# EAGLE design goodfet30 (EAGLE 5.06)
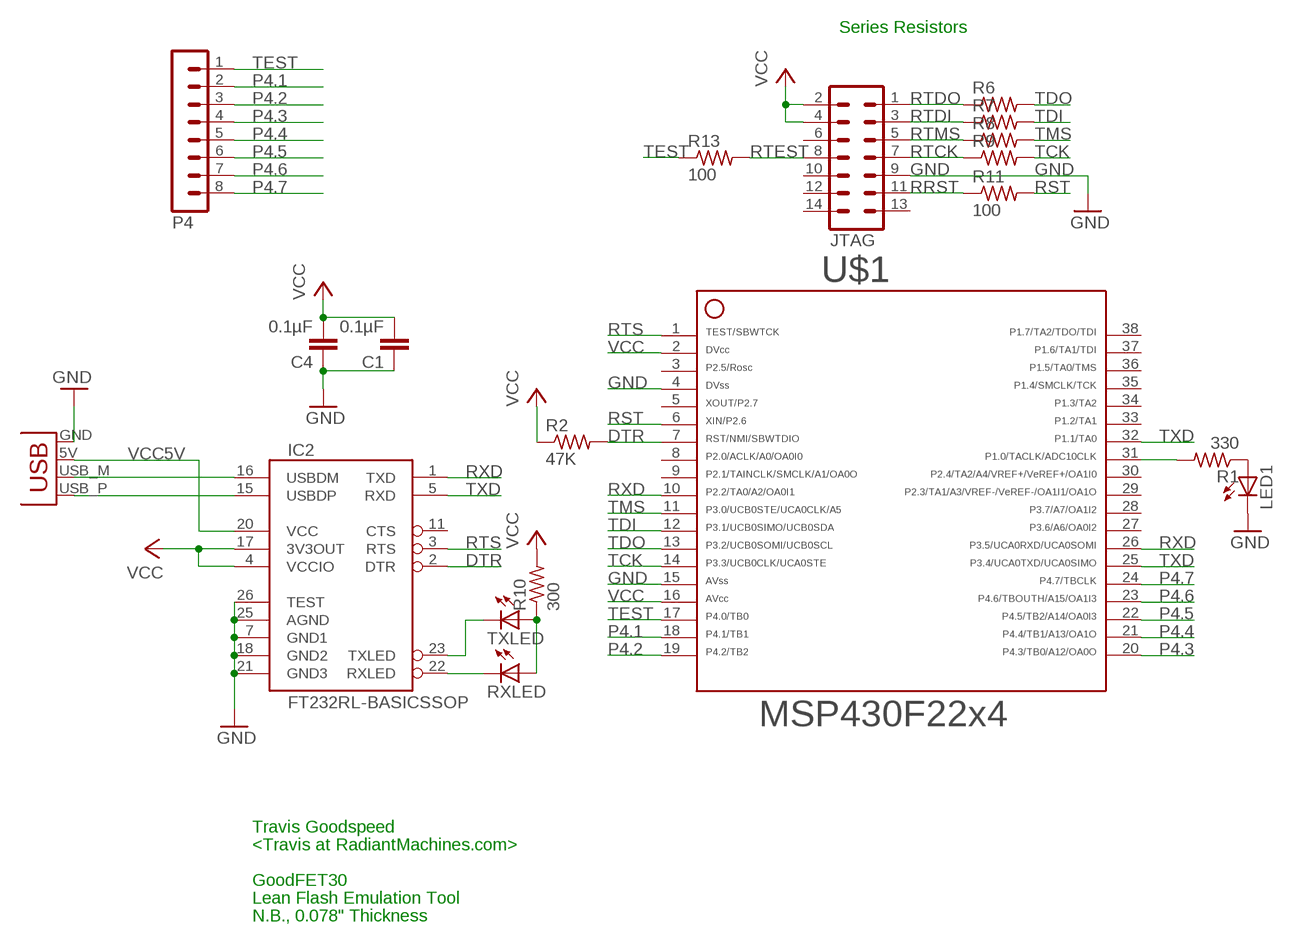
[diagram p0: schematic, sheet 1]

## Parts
C1  0.1µF  C-EUC0603  [C0603]
C4  0.1µF  C-EUC0603  [C0603]
IC2  FT232RL-BASICSSOP  [SSOP28DB]
JTAG  MA07-2  [MA07-2]
LED1  LEDCHIP-LED0603  [CHIP-LED0603]
P4  MA08-1  [MA08-1]
R1  330  R-US_R0603  [R0603]
R2  47K  R-US_R0603  [R0603]
R6  100  R-US_R0603  [R0603]
R7  100  R-US_R0603  [R0603]
R8  100  R-US_R0603  [R0603]
R9  100  R-US_R0603  [R0603]
R10  300  R-US_R0603  [R0603]
R11  100  R-US_R0603  [R0603]
R13  100  R-US_R0603  [R0603]
RXLED  LEDCHIP-LED0603  [CHIP-LED0603]
TXLED  LEDCHIP-LED0603  [CHIP-LED0603]
U$1  F22X4---DA38  [DA38]
X1  USBPCB  [USB-A-PCB]

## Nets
DTR: IC2.2(DTR) R2.2 U$1.7
GND: C1.1 C4.1 IC2.7(GND1) IC2.18(GND2) IC2.21(GND3) IC2.25(AGND) IC2.26(TEST) JTAG.9 LED1.C U$1.4 U$1.15 X1.GND
N$3: IC2.15(USBDP) X1.USB_P(D+)
N$4: IC2.16(USBDM) X1.USB_M(D-)
N$6: IC2.22(RXLED) RXLED.C
N$7: IC2.23(TXLED) TXLED.C
N$8: R10.1 RXLED.A TXLED.A
N$9: R1.2 U$1.31
N$10: LED1.A R1.1
P4.1: P4.2 U$1.18
P4.2: P4.3 U$1.19
P4.3: P4.4 U$1.20
P4.4: P4.5 U$1.21
P4.5: P4.6 U$1.22
P4.6: P4.7 U$1.23
P4.7: P4.8 U$1.24
RRST: JTAG.11 R11.1
RST: R11.2 U$1.6
RTCK: JTAG.7 R9.1
RTDI: JTAG.3 R7.1
RTDO: JTAG.1 R6.1
RTEST: JTAG.8 R13.2
RTMS: JTAG.5 R8.1
RTS: IC2.3(RTS) U$1.1
RXD: IC2.1(TXD) U$1.10 U$1.26
TCK: R9.2 U$1.14
TDI: R7.2 U$1.12
TDO: R6.2 U$1.13
TEST: P4.1 R13.1 U$1.17
TMS: R8.2 U$1.11
TXD: IC2.5(RXD) U$1.25 U$1.32
VCC: C1.2 C4.2 IC2.4(VCCIO) IC2.17(3V3OUT) JTAG.2 JTAG.4 R2.1 R10.2 U$1.2 U$1.16
VCC5V: IC2.20(VCC) X1.5V(VBUS)
Unconnected: IC2.11(CTS) JTAG.6 JTAG.10 JTAG.12 JTAG.13 JTAG.14 U$1.3 U$1.5 U$1.8 U$1.9 U$1.27 U$1.28 U$1.29 U$1.30 U$1.33 U$1.34 U$1.35 U$1.36 U$1.37 U$1.38

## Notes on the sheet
- Series Resistors
- Travis Goodspeed
- <Travis at RadiantMachines.com>
- GoodFET30
- Lean Flash Emulation Tool
- N.B., 0.078" Thickness

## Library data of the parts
C1 C4 = rcl:C-EU: CAPACITOR, European symbol
IC2 = SparkFun:FT232RL-BASIC: USB UART This is the simplified version of the FT232RL unit. Only what you need, nothing you don't. Spark Fun Electronics SKU : COM-00650
JTAG = con-lstb:MA07-2: PIN HEADER
LED1 RXLED TXLED = led:LED: LED
P4 = con-lstb:MA08-1: PIN HEADER
R1 R2 R10 = rcl:R-US_: RESISTOR, American symbol
R6-R9 R11 R13 = resistor:R-US_: RESISTOR, American symbol
U$1 = TI_MSP430_v13:F22X4---DA38: ***MSP430F22x4***DA38
X1 = SparkFun:USB: USB Connectors USB-B-PTH is fully proven SKU : PRT-00139 USB-miniB is fully proven SKU : PRT-00587 USB-A-PCB is untested. USB-A-H is throughly reviewed, but untested. Spark Fun Electronics SKU : PRT-00437 USB-B-SMT is throughly reviewed, but untested. Needs silkscreen touching up. USB-A-S has not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

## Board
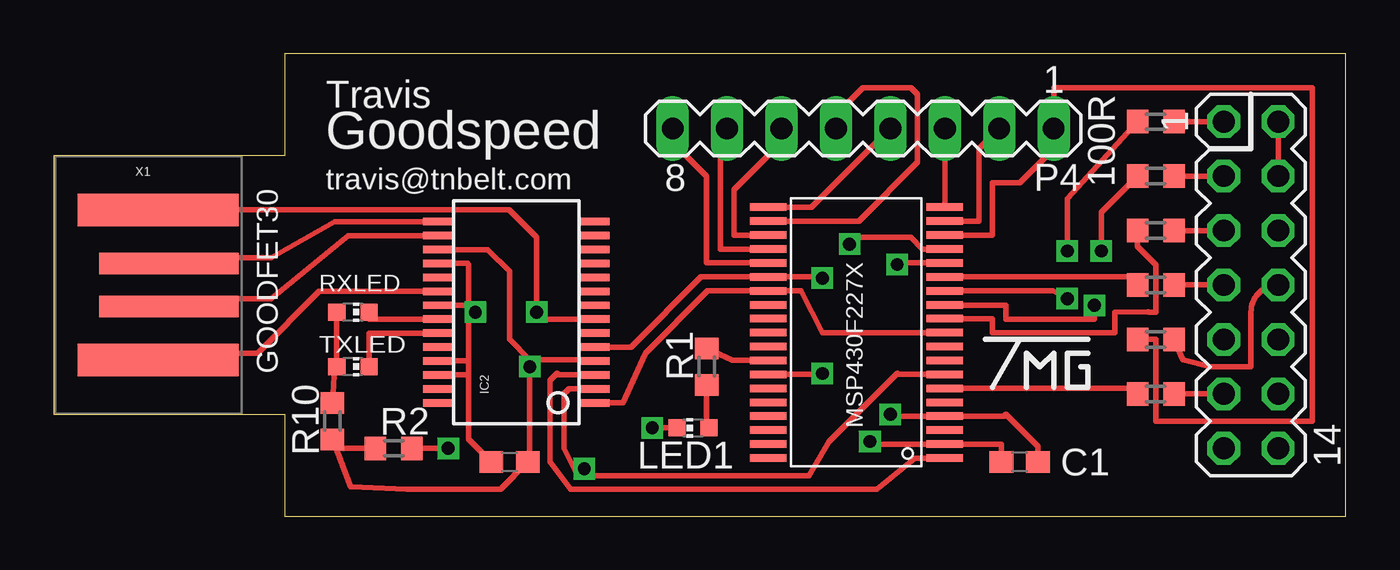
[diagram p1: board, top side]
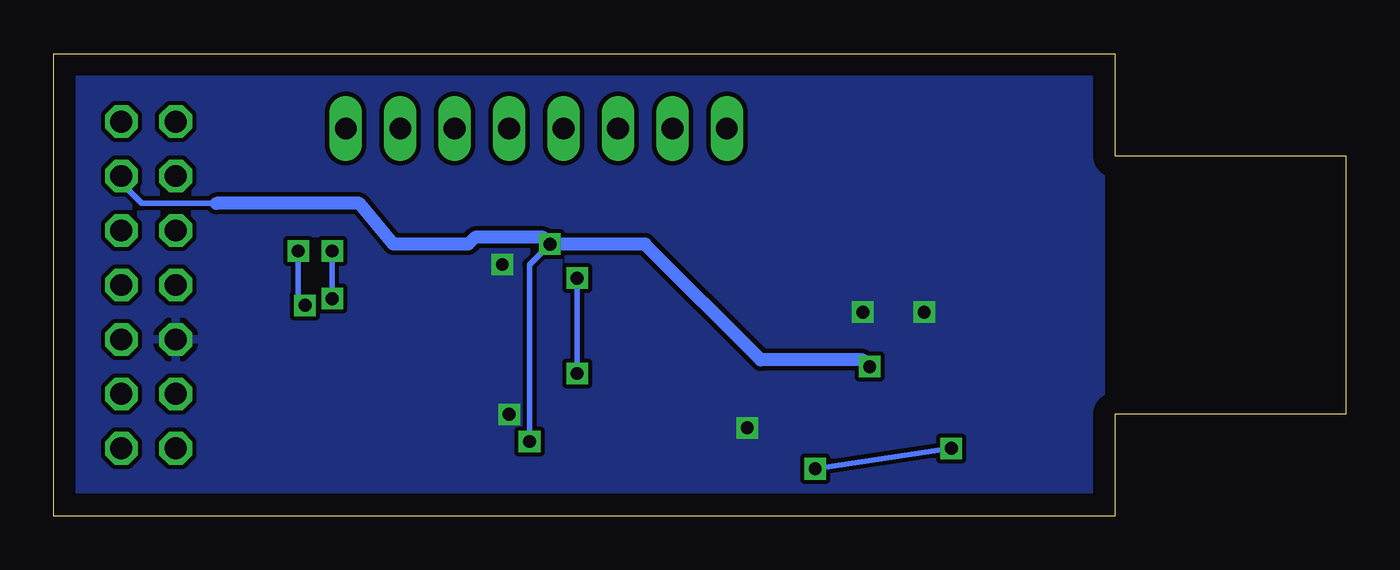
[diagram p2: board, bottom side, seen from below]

Size 60.31 x 21.59 mm. Coordinates in mm from the lower left corner, seen from the top.
Outline: 10.79,0 60.31,0 60.31,21.59 10.79,21.59 10.79,16.83 0,16.83 0,4.76 10.79,4.76 10.79,0
Copper layers (1*16): Top 0.035mm / dielectric 1.5mm / Bottom 0.035mm
Design rules "default *": minimum track width 10mil, minimum drill 10mil, track to track 8mil, track to pad 8mil, pad to pad 8mil, via to via 8mil, smd to smd 8mil, copper to edge 40mil, drill to drill 10mil, minimum pad ring 10mil, minimum via ring 8mil, stop-mask expansion 4mil, vias tented up to drill 0mil, thermal gap 10mil

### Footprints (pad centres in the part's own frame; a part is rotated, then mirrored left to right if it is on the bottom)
C0603 = smd 1.1 x 1: 1 -0.85,0; 2 0.85,0
SSOP28DB = smd 0.348 x 1.397: 1 -4.225,-3.656; 2 -3.575,-3.656; 3 -2.925,-3.656; 4 -2.275,-3.656; 5 -1.625,-3.656; 6 -0.975,-3.656; 7 -0.325,-3.656; 8 0.325,-3.656; 9 0.975,-3.656; 10 1.625,-3.656; 11 2.275,-3.656; 12 2.925,-3.656; 13 3.575,-3.656; 14 4.225,-3.656; 15 4.225,3.656; 16 3.575,3.656; 17 2.925,3.656; 18 2.275,3.656; 19 1.625,3.656; 20 0.975,3.656; 21 0.325,3.656; 22 -0.325,3.656; 23 -0.975,3.656; 24 -1.625,3.656; 25 -2.275,3.656; 26 -2.925,3.656; 27 -3.575,3.656; 28 -4.225,3.656
MA07-2 = drill 1.016 octagon: 1 -7.62,-1.27; 2 -7.62,1.27; 3 -5.08,-1.27; 4 -5.08,1.27; 5 -2.54,-1.27; 6 -2.54,1.27; 7 0,-1.27; 8 0,1.27; 9 2.54,-1.27; 10 2.54,1.27; 11 5.08,-1.27; 12 5.08,1.27; 13 7.62,-1.27; 14 7.62,1.27
CHIP-LED0603 = smd 0.8 x 0.8: A 0,-0.75; C 0,0.75
MA08-1 = drill 1.016 long: 1 -8.89,0; 2 -6.35,0; 3 -3.81,0; 4 -1.27,0; 5 1.27,0; 6 3.81,0; 7 6.35,0; 8 8.89,0
R0603 = smd 1 x 1.1: 1 -0.85,0; 2 0.85,0
DA38 = smd 0.35 x 1.705: 1 -5.85,-4.12; 2 -5.2,-4.12; 3 -4.55,-4.12; 4 -3.9,-4.12; 5 -3.25,-4.12; 6 -2.6,-4.12; 7 -1.95,-4.12; 8 -1.3,-4.12; 9 -0.65,-4.12; 10 0,-4.12; 11 0.65,-4.12; 12 1.3,-4.12; 13 1.95,-4.12; 14 2.6,-4.12; 15 3.25,-4.12; 16 3.9,-4.12; 17 4.55,-4.12; 18 5.2,-4.12; 19 5.85,-4.12; 20 5.85,4.12; 21 5.2,4.12; 22 4.55,4.12; 23 3.9,4.12; 24 3.25,4.12; 25 2.6,4.12; 26 1.95,4.12; 27 1.3,4.12; 28 0.65,4.12; 29 0,4.12; 30 -0.65,4.12; 31 -1.3,4.12; 32 -1.95,4.12; 33 -2.6,4.12; 34 -3.25,4.12; 35 -3.9,4.12; 36 -4.55,4.12; 37 -5.2,4.12; 38 -5.85,4.12
USB-A-PCB = smd 7.5 x 1.5: 5V -0.2,-3.5; GND -0.2,3.5 | smd 6.5 x 1: USB_M 0.3,-1; USB_P 0.3,1

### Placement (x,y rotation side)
C1  45.09,2.54 180 top
C4  21.27,2.54 0 top
IC2  21.59,9.53 90 top
JTAG  55.88,10.79 270 top
LED1  29.85,4.13 90 top
P4  37.78,18.1 180 top
R1  30.48,6.99 90 top
R2  15.88,3.18 0 top
R6  51.44,18.42 180 top
R7  51.44,15.88 180 top
R8  51.44,13.33 180 top
R9  51.44,10.79 180 top
R10  13.02,4.45 270 top
R11  51.44,5.71 180 top
R13  51.44,8.25 0 top
RXLED  13.97,9.53 270 top
TXLED  13.97,6.99 270 top
U$1  37.47,8.57 90 top
X1  5.08,10.79 0 top

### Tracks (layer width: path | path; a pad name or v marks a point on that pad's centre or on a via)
DTR  (via drill 0.6)
  Top 0.254: IC2.2 24.05,5.95 23.81,5.71 23.81,3.18 24.45,1.91 24.76,1.91 | 24.76,1.91 35.24,1.91 36.2,3.49 39.37,6.67 39.41,6.62 U$1.7 | R2.2 v18.41,3.18 | v24.76,2.22 24.76,1.91
  Bottom 0.254: v18.41,3.18 v24.76,2.22
GND  (via drill 0.6)
  Top 0.254: U$1.15 39.45,11.82 v39.37,11.75 | v39.05,4.76 39.05,4.67 U$1.4 44.36,4.67 44.45,4.76 45.94,3.28 C1.1 | IC2.7 22.54,9.2 v22.54,9.53 22.54,13.02 21.27,14.29 X1.GND | IC2.18 19.31,11.8 19.37,11.75 19.37,9.84 | 19.37,6.67 19.37,3.6 C4.1 | 19.37,6.67 19.37,7.3 | 19.37,7.3 19.37,9.84 | IC2.26 19.3,6.6 19.37,6.67 | IC2.25 19.31,7.25 19.37,7.3 | 19.36,9.85 IC2.21 | 19.37,9.84 19.36,9.85 | 19.36,9.85 19.36,9.53 v19.68,9.53 | LED1.C v27.94,4.13
  Bottom 0.254: v39.37,11.75 39.05,11.75 | v39.05,4.76 38.73,4.76 | v22.54,9.53 22.22,9.53 | v19.68,9.53 20,9.53
  pour Bottom: 11.75,20.96 59.37,20.96 59.69,1.27 11.43,1.27 11.43,20.64
N$3
  Top 0.254: IC2.15 13.11,13.75 10.16,12.07 5.65,12.07 X1.USB_P
N$4
  Top 0.254: IC2.16 13.73,13.1 10.16,10.16 5.75,10.16 X1.USB_M
N$6
  Top 0.254: IC2.22 14.72,9.2 RXLED.C
N$7
  Top 0.254: IC2.23 14.72,8.55 TXLED.C
N$8
  Top 0.254: RXLED.A TXLED.A 13.12,6.99 R10.1
N$9
  Top 0.254: U$1.31 31.68,7.27 R1.2
N$10
  Top 0.254: R1.1 30.48,4.33 LED1.A
P4.1
  Top 0.254: U$1.18 43.18,13.77 43.18,17.14 P4.2
P4.2
  Top 0.254: U$1.19 41.59,14.43 P4.3
P4.3
  Top 0.254: U$1.20 35.38,14.42 P4.4
P4.4
  Top 0.254: U$1.21 37.59,13.77 40.32,16.51 40.32,19.68 40.01,20 37.78,20 36.51,18.73 P4.5
P4.5
  Top 0.254: U$1.22 31.75,13.12 31.75,15.24 33.97,17.46 P4.6
P4.6
  Top 0.254: U$1.23 31.11,12.47 31.11,16.83 P4.7
P4.7
  Top 0.254: U$1.24 30.48,11.82 30.48,15.88 28.89,17.46 P4.8
RRST
  Top 0.254: R11.1 JTAG.11
RST
  Top 0.254: U$1.6 50.33,5.97 R11.2
RTCK
  Top 0.254: R9.1 JTAG.7
RTDI
  Top 0.254: R7.1 JTAG.3
RTDO
  Top 0.254: R6.1 JTAG.1
RTEST
  Top 0.254: R13.2 52.71,7.3 53.98,6.99 55.88,6.99 55.88,9.53 arc-90 JTAG.8
RTMS
  Top 0.254: R8.1 JTAG.5
RTS
  Top 0.254: U$1.1 40.19,2.72 38.42,1.27 24.13,1.27 23.18,2.54 23.18,6.35 23.49,6.67 23.56,6.6 IC2.3
RXD
  Top 0.254: IC2.1 26.57,5.3 27.62,7.62 30.53,10.52 U$1.26 34.88,10.52 35.88,8.57 U$1.10
TCK
  Top 0.254: 50.8,10.79 R9.2 50.21,11.17 U$1.14
TDI  (via drill 0.6)
  Top 0.254: R7.2 48.9,14.18 v48.9,12.38 | U$1.12 41.59,9.84 44.45,9.84 44.45,9.21 48.58,9.21 v48.58,9.84
  Bottom 0.254: v48.9,12.38 48.9,9.84 v48.58,9.84
TDO  (via drill 0.6)
  Top 0.254: R6.2 47.31,14.82 v47.31,12.38 | v47.31,10.16 46.63,10.52 U$1.13
  Bottom 0.254: v47.31,10.16 v47.31,12.38
TEST
  Top 0.254: U$1.17 43.82,13.12 43.82,15.56 45.09,15.56 46.67,17.14 P4.1 46.67,20 58.74,20 58.74,4.45 51.44,4.45 51.44,8.25 R13.1
TMS
  Top 0.254: R8.2 50.59,12.6 51.44,11.75 51.44,9.53 51.12,9.53 51.1,9.54 49.53,9.53 49.53,8.57 43.82,8.57 43.82,9.22 U$1.11
TXD  (via drill 0.6)
  Top 0.254: IC2.5 26.95,7.9 30.22,11.17 U$1.25 35.56,11.17 v35.88,11.11 | U$1.32 35.56,6.62 v35.88,6.67
  Bottom 0.254: v35.88,11.11 v35.88,6.67
VCC  (via drill 0.6)
  Top 0.254: JTAG.4 JTAG.2 | IC2.4 25.19,7.3 22.22,7.3 | IC2.17 20.25,12.45 21.27,11.43 21.27,8.25 22.22,7.3 | R2.1 13.44,3.18 R10.2 13.87,1.37 16.51,1.27 20.85,1.27 C4.2 22.22,2.64 v22.22,6.99 22.22,7.3 | U$1.16 40.55,12.47 40.01,13.02 37.47,13.02 v37.15,12.7 | v38.1,3.49 38.22,3.37 U$1.2 44.23,3.37 C1.2
  Bottom 0.254: JTAG.4 57.15,15.56 56.2,14.61 52.71,14.61 | v38.1,3.49 38.1,11.75 v37.15,12.7
  Bottom 0.61: v22.22,6.99 22.54,7.3 27.3,7.3 32.7,12.7 v37.15,12.7 37.47,13.02 40.64,13.02 40.96,12.7 44.45,12.7 46.04,14.61 52.71,14.61
VCC5V
  Top 0.254: IC2.20 12.4,10.5 9.52,7.62 5.2,7.62 X1.5V

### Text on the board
tPlace: Travis | 100R | Goodspeed | travis@tnbelt.com | GOODFET30
tNames: MSP430F227X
